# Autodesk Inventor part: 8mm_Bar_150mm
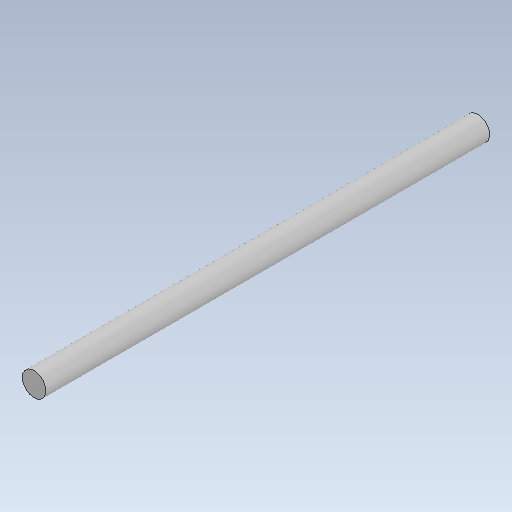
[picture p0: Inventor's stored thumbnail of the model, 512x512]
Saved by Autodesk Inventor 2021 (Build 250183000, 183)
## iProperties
Created: 2026-10
Part Number: 8mm_Bar_150mm
Material: Generic
Document SubType Name: Modeling
Designer: hp
Density: 1 g/cm^3
Appearance: Default
Author: hp
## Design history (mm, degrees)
feature "Body1"
body "Solid1"
